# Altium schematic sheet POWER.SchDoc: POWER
size A3; Author: Arturo Guadalupi; CompanyName: Arduino srl; DocumentNumber: ABX00043; SheetNumber: 12; SheetTotal: 14; RevAuthor: S. Navaretti
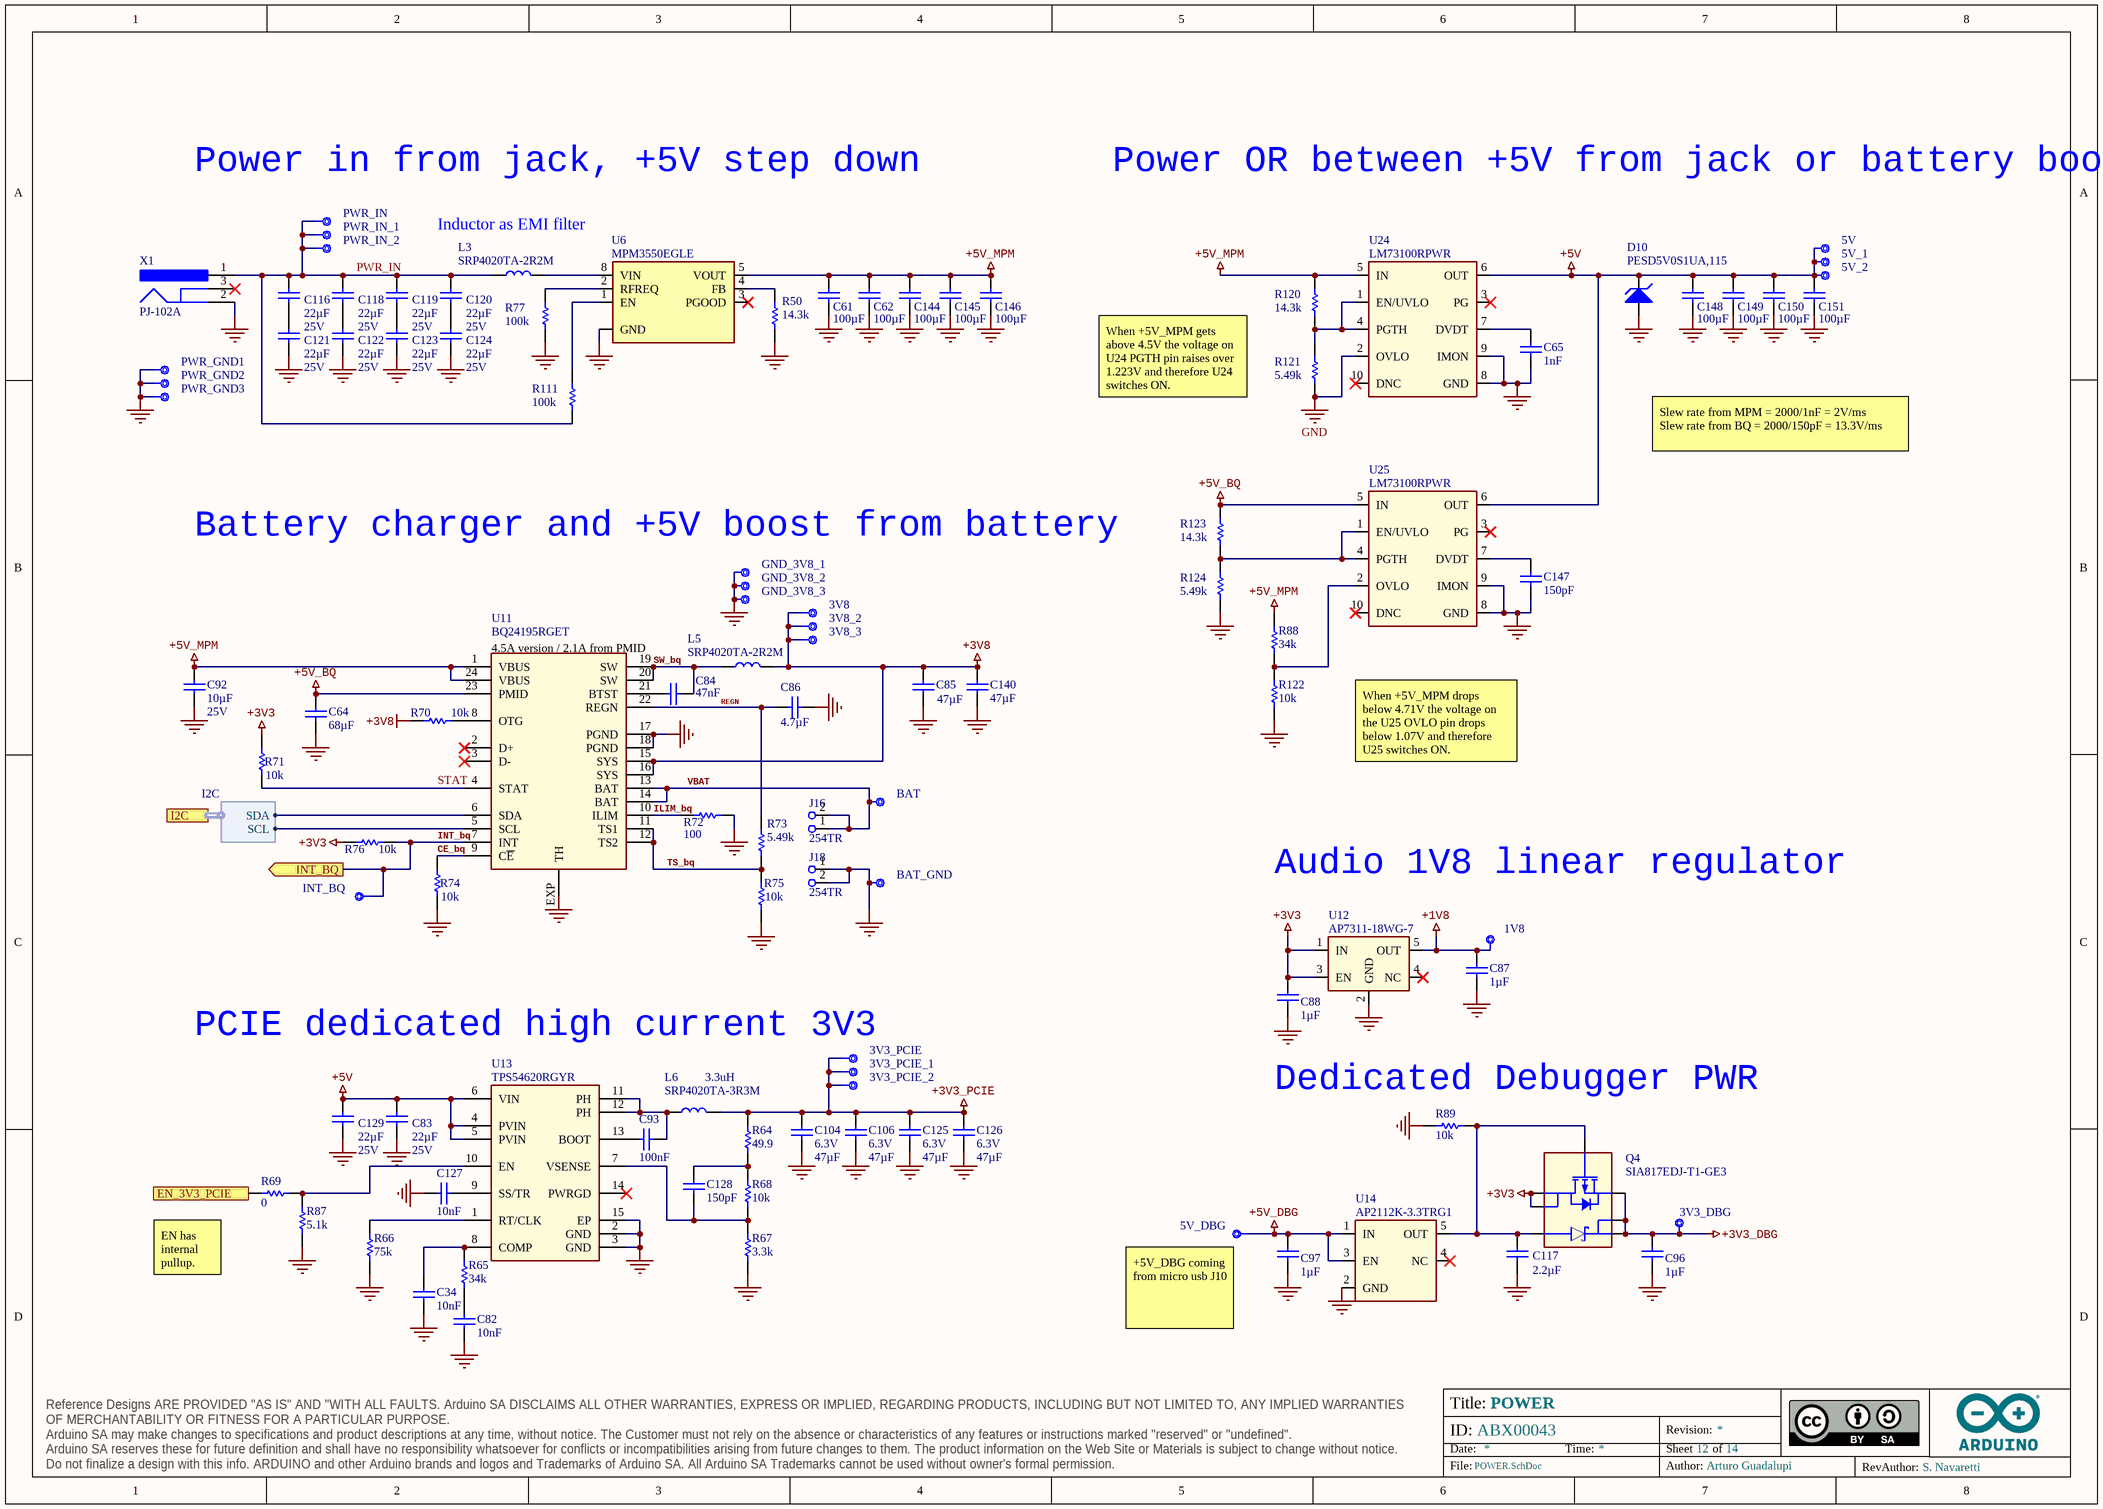
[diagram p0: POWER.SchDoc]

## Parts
1V8  CMP-018-0005-A.3  [TP-1.00MM]  (value not drawn)  (no BOM)
3V3_DBG  CMP-018-0005-A.3  [TP-1.00MM]  (value not drawn)  (no BOM)
3V3_PCIE  CMP-018-0005-A.3  [TP-1.00MM]  (value not drawn)  (no BOM)
3V3_PCIE_1  CMP-018-0005-A.3  [TP-1.00MM]  (value not drawn)  (no BOM)
3V3_PCIE_2  CMP-018-0005-A.3  [TP-1.00MM]  (value not drawn)  (no BOM)
3V8  CMP-018-0005-A.3  [TP-1.00MM]  (value not drawn)  (no BOM)
3V8_2  CMP-018-0005-A.3  [TP-1.00MM]  (value not drawn)  (no BOM)
3V8_3  CMP-018-0005-A.3  [TP-1.00MM]  (value not drawn)  (no BOM)
5V  CMP-018-0005-A.3  [TP-1.00MM]  (value not drawn)  (no BOM)
5V_1  CMP-018-0005-A.3  [TP-1.00MM]  (value not drawn)  (no BOM)
5V_2  CMP-018-0005-A.3  [TP-1.00MM]  (value not drawn)  (no BOM)
5V_DBG  CMP-018-0005-A.3  [TP-1.00MM]  (value not drawn)  (no BOM)
BAT  CMP-018-0005-A.3  [TP-1.00MM]  (value not drawn)  (no BOM)
BAT_GND  CMP-018-0005-A.3  [TP-1.00MM]  (value not drawn)  (no BOM)
C34  value 10nF  [CAP-0402]  (hidden comment: C0402C103K5RACTU)
C61  value 100µF  [CAP-1206]  (hidden comment: CL31A107MPHNNNE)
C62  value 100µF  [CAP-1206]  (hidden comment: CL31A107MPHNNNE)
C64  value 68µF  [CAP-1206]  (hidden comment: C3216X5R1A686M160AC)
C65  value 1nF  [CAP-0402]  (hidden comment: C0402C100K5RACTU)
C82  value 10nF  [CAP-0402]  (hidden comment: C0402C103K5RACTU)
C83  value 22µF  Voltage: 25V  [CAP-0805]  (hidden comment: CL21A226MAQNNNE)
C84  value 47nF  [CAP-0402]  (hidden comment: GRM155R61H473KE14D)
C85  value 47µF  [CAP-0603]  (hidden comment: ZRB18AR60J476ME01L)
C86  value 4.7µF  [CAP-0402]  (hidden comment: GRM155R60J475ME47D)
C87  value 1µF  [CAP-0402]  (hidden comment: C0402C105K8PACTU)
C88  value 1µF  [CAP-0402]  (hidden comment: C0402C105K8PACTU)
C92  value 10µF  Voltage: 25V  [CAP-0603]  (hidden comment: GRM188R61E106MA73J)
C93  value 100nF  [CAP-0402]  (hidden comment: C0402C104K4RACTU)
C96  value 1µF  [CAP-0402]  (hidden comment: C0402C105K8PACTU)
C97  value 1µF  [CAP-0402]  (hidden comment: C0402C105K8PACTU)
C104  value 47µF  Voltage Rating: 6.3V  [CAP-0603]  (hidden comment: ZRB18AR60J476ME01L)
C106  value 47µF  Voltage Rating: 6.3V  [CAP-0603]  (hidden comment: ZRB18AR60J476ME01L)
C116  value 22µF  Voltage: 25V  [CAP-0805]  (hidden comment: CL21A226MAQNNNE)
C117  value 2.2µF  [CAP-0402]  (hidden comment: GRM155R60J225KE95D)
C118  value 22µF  Voltage: 25V  [CAP-0805]  (hidden comment: CL21A226MAQNNNE)
C119  value 22µF  Voltage: 25V  [CAP-0805]  (hidden comment: CL21A226MAQNNNE)
C120  value 22µF  Voltage: 25V  [CAP-0805]  (hidden comment: CL21A226MAQNNNE)
C121  value 22µF  Voltage: 25V  [CAP-0805]  (hidden comment: CL21A226MAQNNNE)
C122  value 22µF  Voltage: 25V  [CAP-0805]  (hidden comment: CL21A226MAQNNNE)
C123  value 22µF  Voltage: 25V  [CAP-0805]  (hidden comment: CL21A226MAQNNNE)
C124  value 22µF  Voltage: 25V  [CAP-0805]  (hidden comment: CL21A226MAQNNNE)
C125  value 47µF  Voltage Rating: 6.3V  [CAP-0603]  (hidden comment: ZRB18AR60J476ME01L)
C126  value 47µF  Voltage Rating: 6.3V  [CAP-0603]  (hidden comment: ZRB18AR60J476ME01L)
C127  value 10nF  [CAP-0402]  (hidden comment: C0402C103K5RACTU)
C128  value 150pF  [CAP-0402]  (hidden comment: GRM1555C1H151FA01D)
C129  value 22µF  Voltage: 25V  [CAP-0805]  (hidden comment: CL21A226MAQNNNE)
C140  value 47µF  [CAP-0603]  (hidden comment: ZRB18AR60J476ME01L)
C144  value 100µF  [CAP-1206]  (hidden comment: CL31A107MPHNNNE)
C145  value 100µF  [CAP-1206]  (hidden comment: CL31A107MPHNNNE)
C146  value 100µF  [CAP-1206]  (hidden comment: CL31A107MPHNNNE)
C147  value 150pF  [CAP-0402]  (hidden comment: GRM1555C1H151FA01D)
C148  value 100µF  [CAP-1206]  (hidden comment: CL31A107MPHNNNE)
C149  value 100µF  [CAP-1206]  (hidden comment: CL31A107MPHNNNE)
C150  value 100µF  [CAP-1206]  (hidden comment: CL31A107MPHNNNE)
C151  value 100µF  [CAP-1206]  (hidden comment: CL31A107MPHNNNE)
D10  PESD5V0S1UA,115  [SOD323]
GND_3V8_1  CMP-018-0005-A.3  [TP-1.00MM]  (value not drawn)  (no BOM)
GND_3V8_2  CMP-018-0005-A.3  [TP-1.00MM]  (value not drawn)  (no BOM)
GND_3V8_3  CMP-018-0005-A.3  [TP-1.00MM]  (value not drawn)  (no BOM)
INT_BQ  CMP-018-0005-A.3  [TP-1.00MM]  (value not drawn)  (no BOM)
J16  254TR  [254TR-Footprint-1]
J18  254TR  [254TR-Footprint-1]
L3  SRP4020TA-2R2M  [SRP4020]
L5  SRP4020TA-2R2M  [SRP4020]
L6  SRP4020TA-3R3M  value 3.3uH  [SRP4020]
PWR_GND1  CMP-018-0005-A.3  [TP-1.00MM]  (value not drawn)  (no BOM)
PWR_GND2  CMP-018-0005-A.3  [TP-1.00MM]  (value not drawn)  (no BOM)
PWR_GND3  CMP-018-0005-A.3  [TP-1.00MM]  (value not drawn)  (no BOM)
PWR_IN  CMP-018-0005-A.3  [TP-1.00MM]  (value not drawn)  (no BOM)
PWR_IN_1  CMP-018-0005-A.3  [TP-1.00MM]  (value not drawn)  (no BOM)
PWR_IN_2  CMP-018-0005-A.3  [TP-1.00MM]  (value not drawn)  (no BOM)
Q4  SIA817EDJ-T1-GE3  [SON65P205X205X75-8N-MWSD]
R50  value 14.3k  [RES-0402]  (hidden comment: CRCW040214K3FKED)
R64  value 49.9  [RES-0402]  (hidden comment: CRCW040249R9FKEDHP)
R65  value 34k  [RES-0402]  (hidden comment: RC0402FR-0734KL)
R66  value 75k  [RES-0402]  (hidden comment: CRCW040275K0FKED)
R67  value 3.3k  [RES-0402]  (hidden comment: RC0402FR-073K3L)
R68  value 10k  [RES-0402]  (hidden comment: CRCW040210K0FKED)
R69  value 0  [RES-0402]  (hidden comment: CRCW04020000Z0EDC)
R70  value 10k  [RES-0402]  (hidden comment: CRCW040210K0FKED)
R71  value 10k  [RES-0402]  (hidden comment: CRCW040210K0FKED)
R72  value 100  [RES-0402]  (hidden comment: CRCW0402100RFKED)
R73  value 5.49k  [RES-0402]  (hidden comment: CRCW04025K49FKED)
R74  value 10k  [RES-0402]  (hidden comment: CRCW040210K0FKED)
R75  value 10k  [RES-0402]  (hidden comment: CRCW040210K0FKED)
R76  value 10k  [RES-0402]  (hidden comment: CRCW040210K0FKED)
R77  value 100k  [RES-0402]  (hidden comment: CRCW0402100KFKEDC)
R87  value 5.1k  [RES-0402]  (hidden comment: RC0402FR-075K1L)
R88  value 34k  [RES-0402]  (hidden comment: RC0402FR-0734KL)
R89  value 10k  [RES-0402]  (hidden comment: CRCW040210K0FKED)
R111  value 100k  [RES-0402]  (hidden comment: CRCW0402100KFKEDC)
R120  value 14.3k  [RES-0402]  (hidden comment: CRCW040214K3FKED)
R121  value 5.49k  [RES-0402]  (hidden comment: CRCW04025K49FKED)
R122  value 10k  [RES-0402]  (hidden comment: CRCW040210K0FKED)
R123  value 14.3k  [RES-0402]  (hidden comment: CRCW040214K3FKED)
R124  value 5.49k  [RES-0402]  (hidden comment: CRCW04025K49FKED)
U6  MPM3550EGLE  [LGA18C100P6X4_1200X1200X360]
U11  BQ24195RGET  [VQFN24]
U12  AP7311-18WG-7  [SOT25]
U13  TPS54620RGYR  [RHL0014A_V]
U14  AP2112K-3.3TRG1  [SOT25]
U24  LM73100RPWR  [QFN50P200X200X100-16N]
U25  LM73100RPWR  [QFN50P200X200X100-16N]
X1  PJ-102A  [CUI-PJ-102A_V]

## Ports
EN_3V3_PCIE (in), I2C (harness I2C), INT_BQ (out)

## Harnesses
I2C: SCL, SDA

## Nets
+1V8: 1V8.X C87.2 U12.5(OUT)
+3V3: C88.1 Q4.D Q4.D2 R71.2 R76.1 U12.1(IN) U12.3(EN)
+3V3_DBG: 3V3_DBG.X C96.2 Q4.K Q4.K2 Q4.S
+3V3_PCIE: 3V3_PCIE.X 3V3_PCIE_1.X 3V3_PCIE_2.X C104.2 C106.2 C125.2 C126.2 L6.2 R64.2
+3V8: 3V8.X 3V8_2.X 3V8_3.X C85.2 C140.2 L5.2 R70.1 U11.15(SYS) U11.16(SYS)
+5V: 5V.X 5V_1.X 5V_2.X C83.2 C129.2 C148.2 C149.2 C150.2 C151.2 D10.2(C) U13.4(PVIN) U13.5(PVIN) U13.6(VIN) U24.6(OUT) U25.6(OUT)
+5V_BQ: C64.2 R123.2 U11.23(PMID) U25.5(IN)
+5V_DBG: 5V_DBG.X C97.1 U14.1(IN) U14.3(EN)
+5V_MPM: C61.2 C62.2 C92.2 C144.2 C145.2 C146.2 R88.2 R120.2 U6.5(VOUT) U11.1(VBUS) U11.24(VBUS) U24.5(IN)
GND: BAT_GND.X C34.1 C61.1 C62.1 C64.1 C65.1 C82.1 C83.1 C85.1 C86.2 C87.1 C88.2 C92.1 C96.1 C97.2 C104.1 C106.1 C117.1 C121.1 C122.1 C123.1 C124.1 C125.1 C126.1 C127.2 C129.1 C140.1 C144.1 C145.1 C146.1 C147.1 C148.1 C149.1 C150.1 C151.1 D10.1(A) GND_3V8_1.X GND_3V8_2.X GND_3V8_3.X J18.1(-) J18.2(GND) PWR_GND1.X PWR_GND2.X PWR_GND3.X R50.1 R66.1 R67.1 R72.2 R74.1 R75.1 R77.1 R87.2 R89.2 R121.1 R122.1 R124.1 U6.GND U11.17(PGND) U11.18(PGND) U11.EXP(TH) U12.2(GND) U13.2(GND) U13.3(GND) U13.15(EP) U14.2(GND) U24.2(OVLO) U24.8(GND) U24.9(IMON) U25.8(GND) U25.9(IMON) X1.2
CE_bq: R74.2 U11.9(C~{E})
EN_3V3_PCIE: R69.1 ; port EN_3V3_PCIE
ILIM_bq: R72.1 U11.10(ILIM)
INT_bq: INT_BQ.X R76.2 U11.7(INT) ; port INT_BQ
PWR_IN: C116.2 C118.2 C119.2 C120.2 L3.1 PWR_IN.X PWR_IN_1.X PWR_IN_2.X R111.1 X1.1
REGN: C86.1 R73.2 U11.22(REGN)
STAT: R71.1 U11.4(STAT)
SW_bq: C84.2 L5.1 U11.19(SW) U11.20(SW)
TS_bq: R73.1 R75.2 U11.11(TS1) U11.12(TS2)
VBAT: BAT.X J16.1(-) J16.2(GND) U11.13(BAT) U11.14(BAT)
NetC34_2: C34.2 R65.2 U13.8(COMP)
NetC65_2: C65.2 U24.7(DVDT)
NetC82_2: C82.2 R65.1
NetC84_1: C84.1 U11.21(BTST)
NetC93_1: C93.1 U13.13(BOOT)
NetC93_2: C93.2 L6.1 U13.11(PH) U13.12(PH)
NetC116_1: C116.1 C121.2
NetC117_2: C117.2 Q4.A Q4.G R89.1 U14.5(OUT)
NetC118_1: C118.1 C122.2
NetC119_1: C119.1 C123.2
NetC120_1: C120.1 C124.2
NetC127_1: C127.1 U13.9(SS/TR)
NetC128_1: C128.1 R67.2 R68.1 U13.7(VSENSE)
NetC128_2: C128.2 R64.1 R68.2
NetC147_2: C147.2 U25.7(DVDT)
NetL3_2: L3.2 U6.8(VIN)
NetR50_2: R50.2 U6.4(FB)
NetR66_2: R66.2 U13.1(RT/CLK)
NetR69_2: R69.2 R87.1 U13.10(EN)
NetR70_2: R70.2 U11.8(OTG)
NetR77_2: R77.2 U6.2(RFREQ)
NetR88_1: R88.1 R122.2 U25.2(OVLO)
NetR111_2: R111.2 U6.1(EN)
NetR120_1: R120.1 R121.2 U24.1(EN/UVLO) U24.4(PGTH)
NetR123_1: R123.1 R124.2 U25.1(EN/UVLO) U25.4(PGTH)
NetU11_5: U11.5(SCL) ; port I2C.SCL
NetU11_6: U11.6(SDA) ; port I2C.SDA

Not connected (* = marked no-connect by the designer): U6 3(PGOOD)*; U11 2(D+)* 3(D-)*; U12 4(NC)*; U13 14(PWRGD)*; U14 4(NC)*; U24 3(PG)* 10(DNC)*; U25 3(PG)* 10(DNC)*; X1 3*

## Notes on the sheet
- Power in from jack, +5V step down
- Power OR between +5V from jack or battery boost
- Inductor as EMI filter
- When +5V_MPM gets above 4.5V the voltage on U24 PGTH pin raises over 1.223V and therefore U24 switches ON.
- Slew rate from MPM = 2000/1nF = 2V/ms
  Slew rate from BQ = 2000/150pF = 13.3V/ms
- Battery charger and +5V boost from battery
- When +5V_MPM drops below 4.71V the voltage on the U25 OVLO pin drops below 1.07V and therefore U25 switches ON.
- Audio 1V8 linear regulator
- PCIE dedicated high current 3V3
- (near R89) Dedicated Debugger PWR
- (near R69) EN has internal pullup.
- (near 5V_DBG) +5V_DBG coming from micro usb J10

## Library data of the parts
1V8 3V3_DBG 3V3_PCIE 3V3_PCIE_1 3V3_PCIE_2 3V8 3V8_2 3V8_3 5V 5V_1 5V_2 BAT BAT_GND GND_3V8_1-GND_3V8_3 INT_BQ PWR_GND1-PWR_GND3 PWR_IN PWR_IN_1 PWR_IN_2 = UT0013-A.2: Test point 1.00mm
5V_DBG = UT0013-A.1: Test point 1.00mm
C34 C82 C127 = C0009-A.9: CAP CHIP 0402 10nF 50V X7R 10%; Manufacturer: KEMET; Code Arduino: 0165
C61 C62 C144-C146 C148-C151 = C0062-A.9: CAP CHIP 1206 100UF 10V X5R 20%; Manufacturer: Samsung; Code Arduino: A5503
C64 = C0116-A.1: CAP CHIP 1206 68UF 10V X5R 20%; Manufacturer: TDK; Code Arduino: C0116
C65 = C0007-A.9: CAP CHIP 0402 1nF 50V X7R 10%; Manufacturer: KEMET; Code Arduino: 2321
C83 C116 C118-C124 C129 = C0111-A.2: CAP CHIP 0805 22uF 25V X5R 20%; Manufacturer: Samsung Electro-Mechanics; Code Arduino: C0111
C84 = C0036-A.9: CAP CHIP 0402 47nF 50V X5R 10%; Manufacturer: Murata; Code Arduino: 2216
C85 C140 = C0098-A.5: CAP CHIP 0603 47UF X5R 20%; Manufacturer: Murata; Voltage Rating: 6.3V; Code Arduino: C0098
C86 = C0037-A.9: CAP CHIP 0402 4.7uF 6V3 X5R 20%; Manufacturer: Murata; Code Arduino: 0833; Voltage: 6.3V
C87 C88 C96 C97 = C0017-A.9: CAP CHIP 0402 1uF 10V X5R 10%; Manufacturer: KEMET; Code Arduino: 0133
C92 = C0047-A.12: CAP CHIP 0603 10uF 25V X5R 20%; Manufacturer: Murata; Part Number: C1608X5R1A226MT000N; Code Arduino: 2213
C93 = C0012-A.9: CAP CHIP 0402 100nF 16V X7R 10%; Manufacturer: KEMET; Code Arduino: 0132
C104 C106 C125 C126 = C0098-A.5: CAP CHIP 0603 47UF X5R 20%; Manufacturer: Murata; Code Arduino: C0098
C117 = C0031-A.9: CAP CHIP 0402 2.2uF 6.3V X5R 10%; Manufacturer: Murata; Code Arduino: A5529
C128 C147 = C0074-A.7: CAP CHIP 0402 150PF 50V C0G 1%; Manufacturer: Murata; Code Arduino: C0074
D10 = D0031-A.3: DIODE TVS 5V 19V SOD323; Manufacturer: Nexperia; Code Arduino: D0031
J16 J18 = J0053-A.5: CONN BATTERY HOLDER 18650 CLIP SMT; Manufacturer: Keystone Electronics; Code Arduino: J0053
L3 L5 = I0017-A.6: IND FIXED 2.2UH 4A 61 MOHM SMD; Manufacturer: Bourns; Code Arduino: 2218
L6 = I0049-A.3: IND FIXED SMD 3.3UH 3.5A 76 mOHM; Manufacturer: Bourns; DC Resistance (DCR): 76mR; Tolerance: 20%; Test Frequency: 100kHz; Current: 4A; Code Arduino: I0049
Q4 = T0010-A.6: MOSFET P-CH 30V 4,5A 65mR SC70-6; Manufacturer: Vishay; Device Type: Mosfet P-CH SMD; Code Arduino: 2220
R50 R120 R123 = R0043-A.4: RES CHIP 0402 14K3 1/16W 1%; Manufacturer: Vishay; Power: 63mW; Code Arduino: R0043
R64 = R0046-A.7: RES CHIP 0402 49R9 1% 1/16W; Manufacturer: Vishay; Working Voltage: 50V; Power Rating: 100mW; Power: 63mW; Temperature Coefficient: 100ppm/°C; Resistance: 49.9R; Code Arduino: A5282
R65 = R0172-A.6: RES CHIP 0402 34K OHM 1% 1/16W; Manufacturer: Yageo; Code Arduino: R0172; Voltage Rating: 50V; Power Rating: 62.5mW; Resistance: 34kR; Max Power Dissipation: 63mW; Temperature Coefficient: 100ppm/°C
R66 = R0037-A.6: RES CHIP 0402 75K 1% 1/16W; Manufacturer: Yageo; Tolerance: 5%; Code Arduino: A5480; Power: 63mW
R67 = R0020-A.5: RES CHIP 0402 3K3 1% 1/16W; Manufacturer: Yageo; Code Arduino: 2232; Power: 63mW
R68 R122 = R0003-A.5: RES CHIP 0402 10K 1% 1/16W; Manufacturer: Vishay; Power: 63mW; Code Arduino: 0136
R69 = R0000-A.5: RES CHIP 0402 0R 1/16W; Manufacturer: Vishay; Code Arduino: 0039; Tolerance: J; Power: 63mW
R70 R71 R74-R76 R89 = R0003-A.5: RES CHIP 0402 10K 1% 1/16W; Manufacturer: Vishay; Code Arduino: 0136; Power: 63mW
R72 = R0031-A.6: RES CHIP 0402 100R 1% 1/16W; Manufacturer: Vishay; Code Arduino: A5343; Power: 63mW
R73 = R0014-A.5: RES CHIP 0402 5K49 1% 1/16W; Manufacturer: Vishay; Code Arduino: 2197; Power: 63mW
R77 R111 = R0001-A.5: RES CHIP 0402 100K 1% 1/16W; Manufacturer: Vishay; Power: 63mW; Code Arduino: 0134
R87 = R0210-A.19: RES CHIP 0402 5k1 1% 1/16W; Manufacturer: YAGEO; Power: 62.5mW; Code Arduino: R0210; Temperature coefficient: 100ppm
R88 = R0172-A.6: RES CHIP 0402 34K OHM 1% 1/16W; Manufacturer: Yageo; Code Arduino: R0172; Power Rating: 62.5mW; Temperature Coefficient: 100ppm/°C; Resistance: 34kR; Voltage Rating: 50V; Max Power Dissipation: 63mW
R121 R124 = R0014-A.5: RES CHIP 0402 5K49 1% 1/16W; Manufacturer: Vishay; Power: 63mW; Code Arduino: 2197
U6 = U0050-A.6: IC DC/DC POWER MODULE 36V 5A LGA18; Manufacturer: MPS; Code Arduino: U0050
U11 = U0194-A.2: IC BATTERY CHARGER 4.5A VQFN24; Manufacturer: Texas Instruments; Code Arduino: U0194
U12 = U0110-A.3: IC V-REG LDO 1.8V 150mA  SOT25; Manufacturer: Diodes Inc; Number of Outputs: 1; Polarity: Positive; Power Dissipation: 640W; Min Input Voltage: 2V; Accuracy: 2%; Quiescent Current: 55uA; Max Power Dissipation: 640mW; Max Input Voltage: 6V; Output Type: Fixed; Code Arduino: U0110; Min Current Limit: 200mA
U13 = U0092-A.5: IC REG BUCK ADJ 6A SYNC 14VQFN; Manufacturer: Texas Instruments; Output Type: Adjustable; Min Input Voltage: 4.5V; Synchronous Rectifier: Yes; Output Voltage: 15V; Operating Supply Voltage: 17V; Number of Outputs: 1; Switching Frequency: 1.6MHz; Quiescent Current: 600uA; Min Output Voltage: 800mV; Code Arduino: U0092
U14 = U0027-A.6: IC V-REG LDO 3V3 600mA +En  SOT25; Manufacturer: Diodes Inc; Code Arduino: 2199
U24 U25 = U0192-A.2: IC IDEAL DIODE 2.3V-23V 5.5A QFN 2mm; Manufacturer: Texas Instruments; Max Supply Voltage: 28V; Code Arduino: U0192
X1 = J0083-A.5: CONN PWR JACK 2X5.5MM SOLDER; Manufacturer: CUI; Insulation Resistance: 50MR; Current Rating: 2.5A; Voltage Rating: 24V; Gender: Male; Shielding: Unshielded; Number of Conductors: 2; Code Arduino: J0083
